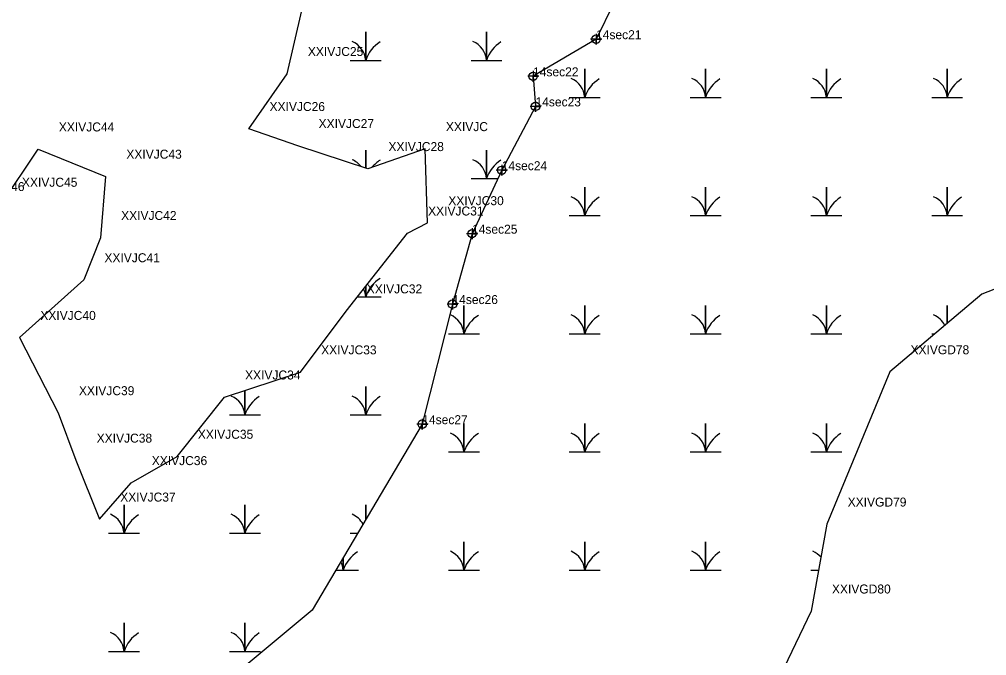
# Model space of a CAD drawing. Extents: x 2071991 to 2268989, y 436479 to 469629.
# Drawn here: x 2263157 to 2263695, y 441828 to 442182 of the extents above; entities that cross this region are included whole.
import ezdxf

# ---------------------------------------------------------------- set-up
doc = ezdxf.new("R2010")
doc.units = 0
for name, color, linetype in [('Exist Environmental Wetland Boundary', 7, 'Continuous'), ('Exist Environmental Wetland Boundary Cogo Comment', 7, 'Continuous'), ('Exist Hydro Jurisdictional Stream or Body of Water NEU Mitigable', 7, 'Continuous'), ('Exist Hydro Jurisdictional Stream or Body of Water NEU Mitigable Cogo Comment', 7, 'Continuous'), ('Exist Hydro Jurisdictional Stream or Body of Water NEU Mitigable Cogo Point CELL', 7, 'Continuous'), ('Exist Hydro Swamp or Marsh', 7, 'Continuous')]:
    doc.layers.add(name, color=color, linetype=linetype)

msp = doc.modelspace()

# ---------------------------------------------------------------- linework, layer by layer
at = {"layer": 'Exist Environmental Wetland Boundary'}
for points in [[(2264311.19, 442631.38), (2264256.71, 442628.32), (2264237.03, 442538.93), (2264188.47, 442538.55), (2264117.97, 442540.24), (2264079.97, 442475.21), (2264007.54, 442425.75), (2263930.27, 442373.75), (2263902.73, 442333.91), (2263891.51, 442275.34), (2263885.59, 442205.4), (2263810.51, 442205.75), (2263787.43, 442192.68), (2263742.82, 442133.35), (2263739.39, 442047.1), (2263692.37, 442028.85), (2263641.17, 441985.48), (2263606.24, 441900.73), (2263597.49, 441852.35), (2263569.3, 441793.49)], [(2263146.91, 442078.7), (2263167.44, 442109.49), (2263204.98, 442094.32), (2263202.07, 442060.21), (2263192.78, 442036.7), (2263157.13, 442004.6), (2263178.6, 441962.71), (2263188.48, 441936.31), (2263201.56, 441903.5), (2263219.1, 441923.8), (2263244.73, 441938.44), (2263271.01, 441971.46), (2263313.34, 441985.43), (2263338.71, 442019.37), (2263372.83, 442062.71), (2263384.08, 442068.46), (2263382.75, 442109.67), (2263350.78, 442098.56), (2263311.92, 442111.37), (2263284.64, 442120.85), (2263305.96, 442151.47), (2263314.06, 442186.63)]]:
    msp.add_lwpolyline(points, dxfattribs=at)
at = {"layer": 'Exist Hydro Jurisdictional Stream or Body of Water NEU Mitigable'}
for points in [[(2263720.2, 442511.78), (2263683.1, 442484.3), (2263639.63, 442454.48), (2263631.34, 442443.68), (2263610.71, 442405.26), (2263589.23, 442357.57), (2263557.85, 442287.71), (2263528.03, 442240.65), (2263519.87, 442221.79), (2263515.9, 442212), (2263505.21, 442205.27), (2263499.32, 442197.98), (2263487.64, 442190.69), (2263477.78, 442170.67), (2263442.74, 442150.01), (2263444.1, 442133.27), (2263425.3, 442097.75), (2263408.78, 442062.43), (2263397.91, 442023.27), (2263381.12, 441956.41)], [(2263381.12, 441956.41), (2263319.77, 441852.83), (2263265.31, 441807.41), (2263142.76, 441712.03), (2263024.75, 441607.57), (2262870.43, 441480.39), (2262729.73, 441316.88), (2262602.64, 441135.21), (2262511.87, 440980.78), (2262461.94, 440849.06), (2262404.53, 440738.7), (2262380.39, 440683.93)]]:
    msp.add_lwpolyline(points, dxfattribs=at)
at = {"layer": 'Exist Hydro Jurisdictional Stream or Body of Water NEU Mitigable Cogo Point CELL'}
for points in [[(2263477.78, 442173.67), (2263477.78, 442167.67), (2263477.78, 442170.67), (2263480.78, 442170.67), (2263474.78, 442170.67)], [(2263442.74, 442153.01), (2263442.74, 442147.01), (2263442.74, 442150.01), (2263445.74, 442150.01), (2263439.74, 442150.01)], [(2263444.1, 442136.27), (2263444.1, 442130.27), (2263444.1, 442133.27), (2263447.1, 442133.27), (2263441.1, 442133.27)], [(2263425.3, 442100.75), (2263425.3, 442094.75), (2263425.3, 442097.75), (2263428.3, 442097.75), (2263422.3, 442097.75)], [(2263408.78, 442065.43), (2263408.78, 442059.43), (2263408.78, 442062.43), (2263411.78, 442062.43), (2263405.78, 442062.43)], [(2263397.91, 442026.27), (2263397.91, 442020.27), (2263397.91, 442023.27), (2263400.91, 442023.27), (2263394.91, 442023.27)], [(2263381.12, 441959.41), (2263381.12, 441953.41), (2263381.12, 441956.41), (2263384.12, 441956.41), (2263378.12, 441956.41)]]:
    msp.add_lwpolyline(points, dxfattribs=at)
for centre in [(2263477.78, 442170.67), (2263442.74, 442150.01), (2263444.1, 442133.27), (2263425.3, 442097.75), (2263408.78, 442062.43), (2263397.91, 442023.27), (2263381.12, 441956.41)]:
    msp.add_circle(centre, 2.34, dxfattribs=at)
at = {"layer": 'Exist Hydro Swamp or Marsh'}
for p, q in [((2263664.5, 442006.75), (2263666.28, 442006.75)), ((2263341.04, 441895.78), (2263345.21, 441895.78)), ((2263597.3, 441875.19), (2263601.62, 441875.19))]:
    msp.add_line(p, q, dxfattribs=at)
for points in [[(2263341.04, 442158.9), (2263349.64, 442158.9), (2263349.64, 442174.68), (2263349.64, 442158.9), (2263358.24, 442158.9)], [(2263408.24, 442158.9), (2263416.84, 442158.9), (2263416.84, 442174.68), (2263416.84, 442158.9), (2263425.44, 442158.9)], [(2263462.89, 442138.31), (2263471.49, 442138.31), (2263471.49, 442154.09), (2263471.49, 442138.31), (2263480.09, 442138.31)], [(2263530.09, 442138.31), (2263538.69, 442138.31), (2263538.69, 442154.09), (2263538.69, 442138.31), (2263547.3, 442138.31)], [(2263597.3, 442138.31), (2263605.9, 442138.31), (2263605.9, 442154.09), (2263605.9, 442138.31), (2263614.5, 442138.31)], [(2263664.5, 442138.31), (2263673.1, 442138.31), (2263673.1, 442154.09), (2263673.1, 442138.31), (2263681.7, 442138.31)], [(2263349.64, 442098.94), (2263349.64, 442108.9), (2263349.64, 442098.94)], [(2263408.24, 442093.12), (2263416.84, 442093.12), (2263416.84, 442108.9), (2263416.84, 442093.12), (2263423.13, 442093.12)], [(2263462.89, 442072.53), (2263471.49, 442072.53), (2263471.49, 442088.31), (2263471.49, 442072.53), (2263480.09, 442072.53)], [(2263530.09, 442072.53), (2263538.69, 442072.53), (2263538.69, 442088.31), (2263538.69, 442072.53), (2263547.3, 442072.53)], [(2263597.3, 442072.53), (2263605.9, 442072.53), (2263605.9, 442088.31), (2263605.9, 442072.53), (2263614.5, 442072.53)], [(2263664.5, 442072.53), (2263673.1, 442072.53), (2263673.1, 442088.31), (2263673.1, 442072.53), (2263681.7, 442072.53)], [(2263344.99, 442027.34), (2263349.64, 442027.34), (2263349.64, 442033.25)], [(2263349.64, 442033.25), (2263349.64, 442027.34), (2263358.24, 442027.34)], [(2263395.69, 442006.75), (2263404.29, 442006.75), (2263404.29, 442022.53), (2263404.29, 442006.75), (2263412.89, 442006.75)], [(2263462.89, 442006.75), (2263471.49, 442006.75), (2263471.49, 442022.53), (2263471.49, 442006.75), (2263480.09, 442006.75)], [(2263530.09, 442006.75), (2263538.69, 442006.75), (2263538.69, 442022.53), (2263538.69, 442006.75), (2263547.3, 442006.75)], [(2263597.3, 442006.75), (2263605.9, 442006.75), (2263605.9, 442022.53), (2263605.9, 442006.75), (2263614.5, 442006.75)], [(2263673.1, 442012.53), (2263673.1, 442022.53), (2263673.1, 442012.53)], [(2263273.83, 441961.56), (2263282.43, 441961.56), (2263282.43, 441975.23)], [(2263282.43, 441975.23), (2263282.43, 441961.56), (2263291.04, 441961.56)], [(2263341.04, 441961.56), (2263349.64, 441961.56), (2263349.64, 441977.34), (2263349.64, 441961.56), (2263358.24, 441961.56)], [(2263395.69, 441940.97), (2263404.29, 441940.97), (2263404.29, 441956.75), (2263404.29, 441940.97), (2263412.89, 441940.97)], [(2263462.89, 441940.97), (2263471.49, 441940.97), (2263471.49, 441956.75), (2263471.49, 441940.97), (2263480.09, 441940.97)], [(2263530.09, 441940.97), (2263538.69, 441940.97), (2263538.69, 441956.75), (2263538.69, 441940.97), (2263547.3, 441940.97)], [(2263597.3, 441940.97), (2263605.9, 441940.97), (2263605.9, 441956.75), (2263605.9, 441940.97), (2263614.5, 441940.97)], [(2263206.63, 441895.78), (2263215.23, 441895.78), (2263215.23, 441911.56), (2263215.23, 441895.78), (2263223.83, 441895.78)], [(2263273.83, 441895.78), (2263282.43, 441895.78), (2263282.43, 441911.56), (2263282.43, 441895.78), (2263291.04, 441895.78)], [(2263349.64, 441903.26), (2263349.64, 441911.56), (2263349.64, 441903.26)], [(2263395.69, 441875.19), (2263404.29, 441875.19), (2263404.29, 441890.97), (2263404.29, 441875.19), (2263412.89, 441875.19)], [(2263462.89, 441875.19), (2263471.49, 441875.19), (2263471.49, 441890.97), (2263471.49, 441875.19), (2263480.09, 441875.19)], [(2263530.09, 441875.19), (2263538.69, 441875.19), (2263538.69, 441890.97), (2263538.69, 441875.19), (2263547.3, 441875.19)], [(2263333.01, 441875.19), (2263337.08, 441875.19), (2263337.08, 441882.06)], [(2263337.08, 441882.06), (2263337.08, 441875.19), (2263345.69, 441875.19)], [(2263206.63, 441830), (2263215.23, 441830), (2263215.23, 441845.78), (2263215.23, 441830), (2263223.83, 441830)], [(2263273.83, 441830), (2263282.43, 441830), (2263282.43, 441845.78), (2263282.43, 441830), (2263291.04, 441830)]]:
    msp.add_lwpolyline(points, dxfattribs=at)
for centre, radius, start, end in [((2263337.37, 442158.01), 12.3, 4.1403, 67.535), ((2263367.88, 442152.84), 19.22, 122.1274, 161.6222), ((2263404.57, 442158.01), 12.3, 4.1403, 67.535), ((2263435.08, 442152.84), 19.22, 122.1274, 161.6222), ((2263459.22, 442137.42), 12.3, 4.1403, 67.535), ((2263489.73, 442132.25), 19.22, 122.1274, 161.6222), ((2263526.43, 442137.42), 12.3, 4.1403, 67.535), ((2263556.94, 442132.25), 19.22, 122.1274, 161.6222), ((2263593.63, 442137.42), 12.3, 4.1403, 67.535), ((2263624.14, 442132.25), 19.22, 122.1274, 161.6222), ((2263660.83, 442137.42), 12.3, 4.1403, 67.535), ((2263691.34, 442132.25), 19.22, 122.1274, 161.6222), ((2263337.37, 442092.23), 12.3, 37.8719, 67.535), ((2263367.88, 442087.06), 19.22, 122.1274, 140.1583), ((2263404.57, 442092.23), 12.3, 4.1403, 67.535), ((2263435.08, 442087.06), 19.22, 122.1274, 161.6222), ((2263459.22, 442071.64), 12.3, 4.1403, 67.535), ((2263526.43, 442071.64), 12.3, 4.1403, 67.535), ((2263593.63, 442071.64), 12.3, 4.1403, 67.535), ((2263660.83, 442071.64), 12.3, 4.1403, 67.535), ((2263489.73, 442066.47), 19.22, 122.1274, 161.6222), ((2263556.94, 442066.47), 19.22, 122.1274, 161.6222), ((2263624.14, 442066.47), 19.22, 122.1274, 161.6222), ((2263691.34, 442066.47), 19.22, 122.1274, 161.6222), ((2263367.88, 442021.28), 19.22, 122.1274, 161.6222), ((2263337.37, 442026.45), 12.3, 4.1403, 25.5695), ((2263392.02, 442005.86), 12.3, 4.1403, 67.535), ((2263422.53, 442000.69), 19.22, 122.1274, 161.6222), ((2263459.22, 442005.86), 12.3, 4.1403, 67.535), ((2263489.73, 442000.69), 19.22, 122.1274, 161.6222), ((2263526.43, 442005.86), 12.3, 4.1403, 67.535), ((2263556.94, 442000.69), 19.22, 122.1274, 161.6222), ((2263593.63, 442005.86), 12.3, 4.1403, 67.535), ((2263624.14, 442000.69), 19.22, 122.1274, 161.6222), ((2263660.83, 442005.86), 12.3, 26.9075, 67.535), ((2263270.17, 441960.67), 12.3, 4.1403, 67.535), ((2263300.68, 441955.5), 19.22, 122.1274, 161.6222), ((2263337.37, 441960.67), 12.3, 4.1403, 67.535), ((2263367.88, 441955.5), 19.22, 122.1274, 161.6222), ((2263392.02, 441940.08), 12.3, 4.1403, 67.535), ((2263422.53, 441934.91), 19.22, 122.1274, 161.6222), ((2263459.22, 441940.08), 12.3, 4.1403, 67.535), ((2263489.73, 441934.91), 19.22, 122.1274, 161.6222), ((2263526.43, 441940.08), 12.3, 4.1403, 67.535), ((2263556.94, 441934.91), 19.22, 122.1274, 161.6222), ((2263593.63, 441940.08), 12.3, 4.1403, 67.535), ((2263624.14, 441934.91), 19.22, 122.1274, 161.6222), ((2263202.97, 441894.89), 12.3, 4.1403, 67.535), ((2263233.47, 441889.72), 19.22, 122.1274, 161.6222), ((2263270.17, 441894.89), 12.3, 4.1403, 67.535), ((2263300.68, 441889.72), 19.22, 122.1274, 161.6222), ((2263337.37, 441894.89), 12.3, 28.599, 67.535), ((2263355.33, 441869.13), 19.22, 122.1274, 161.6222), ((2263392.02, 441874.3), 12.3, 4.1403, 67.535), ((2263422.53, 441869.13), 19.22, 122.1274, 161.6222), ((2263459.22, 441874.3), 12.3, 4.1403, 67.535), ((2263489.73, 441869.13), 19.22, 122.1274, 161.6222), ((2263526.43, 441874.3), 12.3, 4.1403, 67.535), ((2263556.94, 441869.13), 19.22, 122.1274, 161.6222), ((2263593.63, 441874.3), 12.3, 40.9843, 67.535), ((2263324.82, 441874.3), 12.3, 4.1403, 26.9178), ((2263202.97, 441829.11), 12.3, 4.1403, 67.535), ((2263233.47, 441823.94), 19.22, 122.1274, 161.6222), ((2263270.17, 441829.11), 12.3, 4.1403, 67.535), ((2263300.68, 441823.94), 19.22, 122.1274, 161.6222)]:
    msp.add_arc(centre, radius, start, end, dxfattribs=at)

# ---------------------------------------------------------------- texts
at = {"layer": 'Exist Environmental Wetland Boundary Cogo Comment'}
for s, p in [('XXIVJC25 ', (2263317.46, 442161.31)), ('XXIVJC26 ', (2263296.15, 442130.69)), ('XXIVJC27 ', (2263323.43, 442121.22)), ('XXIVJC44 ', (2263178.94, 442119.33)), ('XXIVJC ', (2263394.26, 442119.51)), ('XXIVJC28 ', (2263362.29, 442108.4)), ('XXIVJC43 ', (2263216.49, 442104.17)), ('XXIVJC45 ', (2263158.42, 442088.54)), ('XXIVJC46 ', (2263128.99, 442086.16)), ('XXIVJC30 ', (2263395.59, 442078.3)), ('XXIVJC31 ', (2263384.34, 442072.55)), ('XXIVJC42 ', (2263213.58, 442070.05)), ('XXIVJC41 ', (2263204.29, 442046.54)), ('XXIVJC32 ', (2263350.22, 442029.21)), ('XXIVJC40 ', (2263168.64, 442014.44)), ('XXIVJC33 ', (2263324.85, 441995.27)), ('XXIVGD78 ', (2263652.68, 441995.32)), ('XXIVJC34 ', (2263282.52, 441981.3)), ('XXIVJC39 ', (2263190.11, 441972.55)), ('XXIVJC38 ', (2263199.99, 441946.15)), ('XXIVJC35 ', (2263256.24, 441948.29)), ('XXIVJC36 ', (2263230.62, 441933.64)), ('XXIVJC37 ', (2263213.07, 441913.35)), ('XXIVGD79 ', (2263617.75, 441910.57)), ('XXIVGD80 ', (2263609, 441862.19))]:
    msp.add_text(s, height=5, dxfattribs=at).set_placement(p)
at = {"layer": 'Exist Hydro Jurisdictional Stream or Body of Water NEU Mitigable Cogo Comment'}
for s, p in [('14sec21', (2263477.78, 442170.67)), ('14sec22', (2263442.74, 442150.01)), ('14sec23', (2263444.1, 442133.27)), ('14sec24', (2263425.3, 442097.75)), ('14sec25', (2263408.78, 442062.43)), ('14sec26', (2263397.91, 442023.27)), ('14sec27', (2263381.12, 441956.41))]:
    msp.add_text(s, height=5, dxfattribs=at).set_placement(p)

doc.saveas('drawing.dxf')
